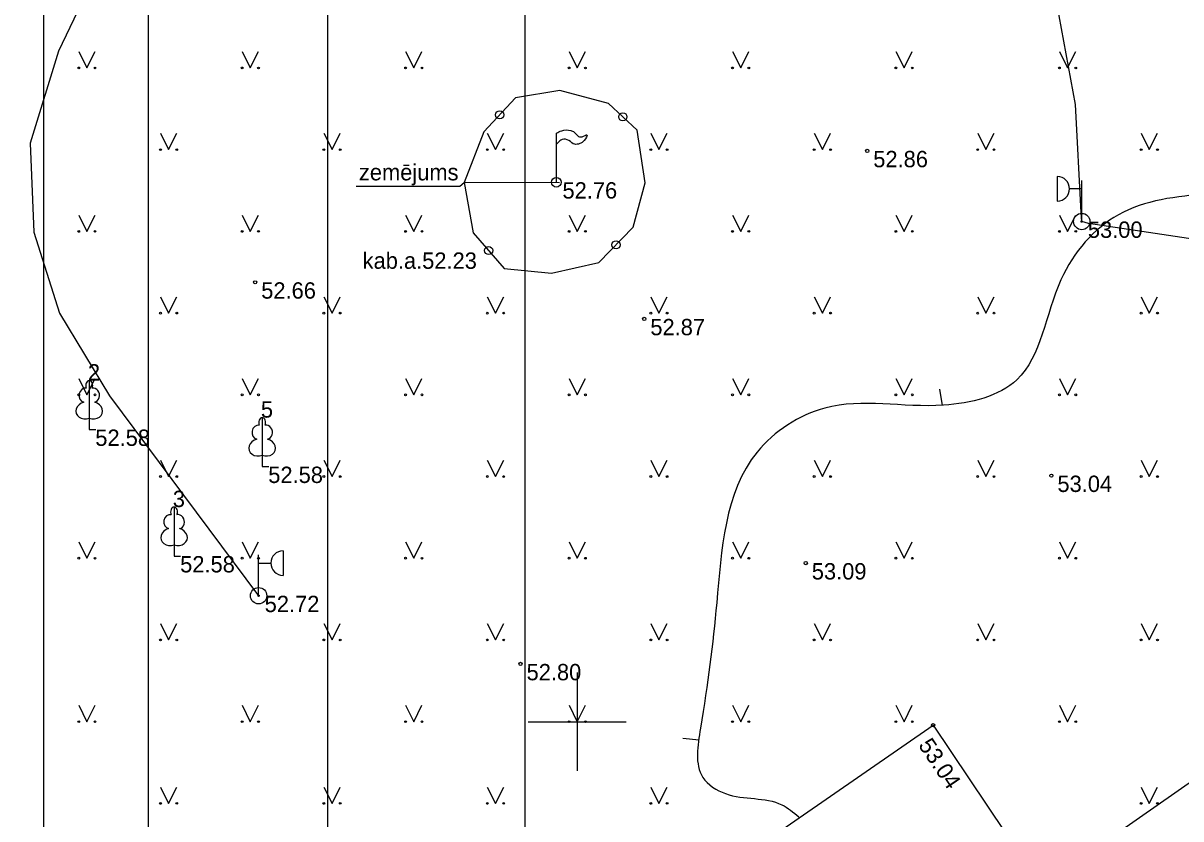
# Model space of a CAD drawing. Extents: x 619806 to 620082, y 405176 to 405386.
# Drawn here: x 619933.05 to 619968.46, y 405297.03 to 405321.37 of the extents above; entities that cross this region are included whole.
import ezdxf

# ---------------------------------------------------------------- set-up
doc = ezdxf.new("R2010")
doc.units = 0
for name, color, linetype in [('APGS_ELEM_####_####_#', 7, 'Continuous'), ('APGS_VADP_ZSPR_####_I', 7, 'Continuous'), ('BUVE_ELEM_####_####_#', 7, 'Continuous'), ('CELI_CMAL_####_####_#', 7, 'Continuous'), ('CKOM_ELEM_####_####_#', 7, 'Continuous'), ('CKOM_ZEMJ_####_####_#', 7, 'Continuous'), ('CKOM_ZEMJ_####_TKST_#', 7, 'Continuous'), ('GEOD_ELEM_####_####_#', 7, 'Continuous'), ('RAMI_PLAN_####_TKST_#', 7, 'Continuous'), ('RELJ_AATZ_####_TKST_#', 7, 'Continuous'), ('RELJ_ELEM_####_####_#', 7, 'Continuous'), ('RELJ_HORZ_PAMT_####_#', 7, 'Continuous'), ('TERT_DIAM_####_TKST_#', 7, 'Continuous'), ('TERT_ELEM_####_####_#', 7, 'Continuous')]:
    doc.layers.add(name, color=color, linetype=linetype)

msp = doc.modelspace()

# ---------------------------------------------------------------- linework, layer by layer
at = {"layer": 'APGS_ELEM_####_####_#'}
for p, q in [((619964.685, 405316.677), (619964.685, 405315.927)), ((619965.435, 405315.302), (619965.435, 405316.552)), ((619965.435, 405316.302), (619965.06, 405316.302)), ((619941.003, 405305.227), (619941.003, 405304.477)), ((619940.253, 405303.852), (619940.253, 405305.102)), ((619940.253, 405304.852), (619940.628, 405304.852))]:
    msp.add_line(p, q, dxfattribs=at)
for centre, radius in [((619965.435, 405315.302), 0.25), ((619965.435, 405315.302), 0.0225), ((619940.253, 405303.852), 0.25), ((619940.253, 405303.852), 0.0225)]:
    msp.add_circle(centre, radius, dxfattribs=at)
for centre, start, end in [((619964.685, 405316.302), 270, 90), ((619941.003, 405304.852), 90, 270)]:
    msp.add_arc(centre, 0.375, start, end, dxfattribs=at)
at = {"layer": 'APGS_VADP_ZSPR_####_I'}
for points in [[(619935.65, 405323.694), (619934.135, 405320.515), (619933.268, 405317.7), (619933.38, 405314.98), (619934.16, 405312.498), (619935.696, 405309.965), (619940.253, 405303.852)], [(619972.163, 405314.266), (619965.642, 405315.238), (619965.435, 405315.302), (619965.418, 405315.579), (619965.238, 405318.885), (619964.67, 405321.977)]]:
    msp.add_lwpolyline(points, dxfattribs=at)
at = {"layer": 'BUVE_ELEM_####_####_#'}
for p, q in [((619949.363, 405317.667), (619949.363, 405318.004)), ((619949.363, 405316.504), (619949.363, 405317.667))]:
    msp.add_line(p, q, dxfattribs=at)
msp.add_circle((619949.363, 405316.504), 0.148, dxfattribs=at)
msp.add_spline([(619949.363, 405318.004), (619949.525, 405318.078), (619949.801, 405318.087), (619949.907, 405318.034), (619950.044, 405317.907), (619950.149, 405317.895), (619950.299, 405317.952), (619950.213, 405317.78), (619950.076, 405317.685), (619949.924, 405317.664), (619949.748, 405317.78), (619949.536, 405317.806), (619949.468, 405317.765), (619949.363, 405317.667)], degree=3, dxfattribs=at)
at = {"layer": 'CELI_CMAL_####_####_#'}
msp.add_lwpolyline([(619951.468, 405293.381), (619960.885, 405299.892), (619964.19, 405294.965), (619971.285, 405299.927), (619977.055, 405303.943), (619973.673, 405308.787), (619991.854, 405321.355)], dxfattribs=at)
at = {"layer": 'CKOM_ELEM_####_####_#'}
for centre in [(619947.63, 405318.567), (619951.395, 405318.505), (619947.29, 405314.413), (619951.187, 405314.589)]:
    msp.add_circle(centre, 0.125, dxfattribs=at)
at = {"layer": 'CKOM_ZEMJ_####_####_#'}
msp.add_lwpolyline([(619949.455, 405316.486), (619946.54, 405316.495), (619946.816, 405314.959), (619947.764, 405313.868), (619949.217, 405313.72), (619950.66, 405314.051), (619951.714, 405315.127), (619952.08, 405316.486), (619951.831, 405318.095), (619950.958, 405318.914), (619949.472, 405319.305), (619948.114, 405319.086), (619947.145, 405318.049), (619946.54, 405316.495)], dxfattribs=at)
at = {"layer": 'CKOM_ZEMJ_####_TKST_#'}
for p, q in [((619943.242, 405316.387), (619946.408, 405316.387)), ((619946.408, 405316.387), (619946.54, 405316.495))]:
    msp.add_line(p, q, dxfattribs=at)
at = {"layer": 'GEOD_ELEM_####_####_#'}
for p, q in [((619950, 405301.5), (619950, 405300)), ((619948.5, 405300), (619950, 405300)), ((619950, 405300), (619950, 405298.5)), ((619950, 405300), (619951.5, 405300))]:
    msp.add_line(p, q, dxfattribs=at)
at = {"layer": 'RAMI_PLAN_####_TKST_#'}
msp.add_line((619942.357, 405361.716), (619942.357, 405215.404), dxfattribs=at)
for points in [[(619933.685, 405385.595), (620082.185, 405385.595), (620082.185, 405175.595), (619933.685, 405175.595)], [(619805.793, 405180.095), (619805.793, 405373.209), (619948.393, 405373.209), (619948.393, 405180.095)], [(619936.885, 405180.095), (619936.885, 405373.209), (620079.485, 405373.209), (620079.485, 405180.095)]]:
    msp.add_lwpolyline(points, close=True, dxfattribs=at)
at = {"layer": 'RELJ_ELEM_####_####_#'}
for centre in [(619958.87, 405317.462), (619940.148, 405313.442), (619952.051, 405312.322), (619964.504, 405307.527), (619956.99, 405304.85), (619948.265, 405301.766), (619960.885, 405299.892)]:
    msp.add_circle(centre, 0.05, dxfattribs=at)
at = {"layer": 'RELJ_HORZ_PAMT_####_#'}
for p, q in [((619961.087, 405310.169), (619961.165, 405309.675)), ((619953.233, 405299.495), (619953.731, 405299.445))]:
    msp.add_line(p, q, dxfattribs=at)
msp.add_spline([(619981.917, 405331.06), (619983.458, 405327.733), (619983.458, 405326.44), (619981.371, 405324.921), (619975.066, 405321.914), (619973.572, 405320.043), (619972.785, 405317.322), (619969.353, 405316.166), (619966.558, 405315.51), (619964.797, 405313.519), (619963.449, 405310.459), (619961.207, 405309.682), (619957.576, 405309.593), (619955.503, 405308.248), (619954.267, 405303.638), (619953.77, 405299.801), (619953.847, 405298.296), (619954.537, 405297.798), (619956.258, 405297.458), (619956.781, 405297.091)], degree=3, dxfattribs=at)
at = {"layer": 'TERT_ELEM_####_####_#'}
for p, q in [((619934.75, 405320.5), (619935, 405320)), ((619935, 405320), (619935.25, 405320.5)), ((619939.75, 405320.5), (619940, 405320)), ((619940, 405320), (619940.25, 405320.5)), ((619944.75, 405320.5), (619945, 405320)), ((619945, 405320), (619945.25, 405320.5)), ((619949.75, 405320.5), (619950, 405320)), ((619950, 405320), (619950.25, 405320.5)), ((619954.75, 405320.5), (619955, 405320)), ((619955, 405320), (619955.25, 405320.5)), ((619959.75, 405320.5), (619960, 405320)), ((619960, 405320), (619960.25, 405320.5)), ((619964.75, 405320.5), (619965, 405320)), ((619965, 405320), (619965.25, 405320.5)), ((619937.25, 405318), (619937.5, 405317.5)), ((619937.5, 405317.5), (619937.75, 405318)), ((619942.25, 405318), (619942.5, 405317.5)), ((619942.5, 405317.5), (619942.75, 405318)), ((619947.25, 405318), (619947.5, 405317.5)), ((619947.5, 405317.5), (619947.75, 405318)), ((619952.25, 405318), (619952.5, 405317.5)), ((619952.5, 405317.5), (619952.75, 405318)), ((619957.25, 405318), (619957.5, 405317.5)), ((619957.5, 405317.5), (619957.75, 405318)), ((619962.25, 405318), (619962.5, 405317.5)), ((619962.5, 405317.5), (619962.75, 405318)), ((619967.25, 405318), (619967.5, 405317.5)), ((619967.5, 405317.5), (619967.75, 405318)), ((619934.75, 405315.5), (619935, 405315)), ((619935, 405315), (619935.25, 405315.5)), ((619939.75, 405315.5), (619940, 405315)), ((619940, 405315), (619940.25, 405315.5)), ((619944.75, 405315.5), (619945, 405315)), ((619945, 405315), (619945.25, 405315.5)), ((619949.75, 405315.5), (619950, 405315)), ((619950, 405315), (619950.25, 405315.5)), ((619954.75, 405315.5), (619955, 405315)), ((619955, 405315), (619955.25, 405315.5)), ((619959.75, 405315.5), (619960, 405315)), ((619960, 405315), (619960.25, 405315.5)), ((619964.75, 405315.5), (619965, 405315)), ((619965, 405315), (619965.25, 405315.5)), ((619937.25, 405313), (619937.5, 405312.5)), ((619937.5, 405312.5), (619937.75, 405313)), ((619942.25, 405313), (619942.5, 405312.5)), ((619942.5, 405312.5), (619942.75, 405313)), ((619947.25, 405313), (619947.5, 405312.5)), ((619947.5, 405312.5), (619947.75, 405313)), ((619952.25, 405313), (619952.5, 405312.5)), ((619952.5, 405312.5), (619952.75, 405313)), ((619957.25, 405313), (619957.5, 405312.5)), ((619957.5, 405312.5), (619957.75, 405313)), ((619962.25, 405313), (619962.5, 405312.5)), ((619962.5, 405312.5), (619962.75, 405313)), ((619967.25, 405313), (619967.5, 405312.5)), ((619967.5, 405312.5), (619967.75, 405313)), ((619934.75, 405310.5), (619935, 405310)), ((619935, 405310), (619935.25, 405310.5)), ((619939.75, 405310.5), (619940, 405310)), ((619940, 405310), (619940.25, 405310.5)), ((619944.75, 405310.5), (619945, 405310)), ((619945, 405310), (619945.25, 405310.5)), ((619949.75, 405310.5), (619950, 405310)), ((619950, 405310), (619950.25, 405310.5)), ((619954.75, 405310.5), (619955, 405310)), ((619955, 405310), (619955.25, 405310.5)), ((619959.75, 405310.5), (619960, 405310)), ((619960, 405310), (619960.25, 405310.5)), ((619964.75, 405310.5), (619965, 405310)), ((619965, 405310), (619965.25, 405310.5)), ((619935.072, 405309.284), (619935.072, 405308.937)), ((619935.072, 405308.937), (619935.272, 405308.937)), ((619940.363, 405308.149), (619940.363, 405307.802)), ((619937.25, 405308), (619937.5, 405307.5)), ((619937.5, 405307.5), (619937.75, 405308)), ((619940.363, 405307.802), (619940.563, 405307.802)), ((619942.25, 405308), (619942.5, 405307.5)), ((619942.5, 405307.5), (619942.75, 405308)), ((619947.25, 405308), (619947.5, 405307.5)), ((619947.5, 405307.5), (619947.75, 405308)), ((619952.25, 405308), (619952.5, 405307.5)), ((619952.5, 405307.5), (619952.75, 405308)), ((619957.25, 405308), (619957.5, 405307.5)), ((619957.5, 405307.5), (619957.75, 405308)), ((619962.25, 405308), (619962.5, 405307.5)), ((619962.5, 405307.5), (619962.75, 405308)), ((619967.25, 405308), (619967.5, 405307.5)), ((619967.5, 405307.5), (619967.75, 405308)), ((619934.75, 405305.5), (619935, 405305)), ((619935, 405305), (619935.25, 405305.5)), ((619937.668, 405305.413), (619937.668, 405305.066)), ((619939.75, 405305.5), (619940, 405305)), ((619940, 405305), (619940.25, 405305.5)), ((619944.75, 405305.5), (619945, 405305)), ((619945, 405305), (619945.25, 405305.5)), ((619949.75, 405305.5), (619950, 405305)), ((619950, 405305), (619950.25, 405305.5)), ((619954.75, 405305.5), (619955, 405305)), ((619955, 405305), (619955.25, 405305.5)), ((619959.75, 405305.5), (619960, 405305)), ((619960, 405305), (619960.25, 405305.5)), ((619964.75, 405305.5), (619965, 405305)), ((619965, 405305), (619965.25, 405305.5)), ((619937.668, 405305.066), (619937.868, 405305.066)), ((619937.25, 405303), (619937.5, 405302.5)), ((619937.5, 405302.5), (619937.75, 405303)), ((619942.25, 405303), (619942.5, 405302.5)), ((619942.5, 405302.5), (619942.75, 405303)), ((619947.25, 405303), (619947.5, 405302.5)), ((619947.5, 405302.5), (619947.75, 405303)), ((619952.25, 405303), (619952.5, 405302.5)), ((619952.5, 405302.5), (619952.75, 405303)), ((619957.25, 405303), (619957.5, 405302.5)), ((619957.5, 405302.5), (619957.75, 405303)), ((619962.25, 405303), (619962.5, 405302.5)), ((619962.5, 405302.5), (619962.75, 405303)), ((619967.25, 405303), (619967.5, 405302.5)), ((619967.5, 405302.5), (619967.75, 405303)), ((619934.75, 405300.5), (619935, 405300)), ((619935, 405300), (619935.25, 405300.5)), ((619939.75, 405300.5), (619940, 405300)), ((619940, 405300), (619940.25, 405300.5)), ((619944.75, 405300.5), (619945, 405300)), ((619945, 405300), (619945.25, 405300.5)), ((619949.75, 405300.5), (619950, 405300)), ((619950, 405300), (619950.25, 405300.5)), ((619954.75, 405300.5), (619955, 405300)), ((619955, 405300), (619955.25, 405300.5)), ((619959.75, 405300.5), (619960, 405300)), ((619960, 405300), (619960.25, 405300.5)), ((619964.75, 405300.5), (619965, 405300)), ((619965, 405300), (619965.25, 405300.5)), ((619937.25, 405298), (619937.5, 405297.5)), ((619937.5, 405297.5), (619937.75, 405298)), ((619942.25, 405298), (619942.5, 405297.5)), ((619942.5, 405297.5), (619942.75, 405298)), ((619947.25, 405298), (619947.5, 405297.5)), ((619947.5, 405297.5), (619947.75, 405298)), ((619952.25, 405298), (619952.5, 405297.5)), ((619952.5, 405297.5), (619952.75, 405298)), ((619967.25, 405298), (619967.5, 405297.5)), ((619967.5, 405297.5), (619967.75, 405298))]:
    msp.add_line(p, q, dxfattribs=at)
for points in [[(619935.072, 405310.437), (619935.072, 405309.284)], [(619935.162, 405310.205), (619935.161, 405310.206)], [(619940.363, 405309.302), (619940.363, 405308.149)], [(619940.453, 405309.07), (619940.452, 405309.071)], [(619937.668, 405306.566), (619937.668, 405305.413)], [(619937.758, 405306.334), (619937.757, 405306.335)]]:
    msp.add_lwpolyline(points, dxfattribs=at)
for centre, radius in [((619934.75, 405320), 0.028), ((619935.25, 405320), 0.0263), ((619939.75, 405320), 0.028), ((619940.25, 405320), 0.0263), ((619944.75, 405320), 0.028), ((619945.25, 405320), 0.0263), ((619949.75, 405320), 0.028), ((619950.25, 405320), 0.0263), ((619954.75, 405320), 0.028), ((619955.25, 405320), 0.0263), ((619959.75, 405320), 0.028), ((619960.25, 405320), 0.0263), ((619964.75, 405320), 0.028), ((619965.25, 405320), 0.0263), ((619937.25, 405317.5), 0.028), ((619937.75, 405317.5), 0.0263), ((619942.25, 405317.5), 0.028), ((619942.75, 405317.5), 0.0263), ((619947.25, 405317.5), 0.028), ((619947.75, 405317.5), 0.0263), ((619952.25, 405317.5), 0.028), ((619952.75, 405317.5), 0.0263), ((619957.25, 405317.5), 0.028), ((619957.75, 405317.5), 0.0263), ((619962.25, 405317.5), 0.028), ((619962.75, 405317.5), 0.0263), ((619967.25, 405317.5), 0.028), ((619967.75, 405317.5), 0.0263), ((619934.75, 405315), 0.028), ((619935.25, 405315), 0.0263), ((619939.75, 405315), 0.028), ((619940.25, 405315), 0.0263), ((619944.75, 405315), 0.028), ((619945.25, 405315), 0.0263), ((619949.75, 405315), 0.028), ((619950.25, 405315), 0.0263), ((619954.75, 405315), 0.028), ((619955.25, 405315), 0.0263), ((619959.75, 405315), 0.028), ((619960.25, 405315), 0.0263), ((619964.75, 405315), 0.028), ((619965.25, 405315), 0.0263), ((619937.25, 405312.5), 0.028), ((619937.75, 405312.5), 0.0263), ((619942.25, 405312.5), 0.028), ((619942.75, 405312.5), 0.0263), ((619947.25, 405312.5), 0.028), ((619947.75, 405312.5), 0.0263), ((619952.25, 405312.5), 0.028), ((619952.75, 405312.5), 0.0263), ((619957.25, 405312.5), 0.028), ((619957.75, 405312.5), 0.0263), ((619962.25, 405312.5), 0.028), ((619962.75, 405312.5), 0.0263), ((619967.25, 405312.5), 0.028), ((619967.75, 405312.5), 0.0263), ((619934.75, 405310), 0.028), ((619935.25, 405310), 0.0263), ((619939.75, 405310), 0.028), ((619940.25, 405310), 0.0263), ((619944.75, 405310), 0.028), ((619945.25, 405310), 0.0263), ((619949.75, 405310), 0.028), ((619950.25, 405310), 0.0263), ((619954.75, 405310), 0.028), ((619955.25, 405310), 0.0263), ((619959.75, 405310), 0.028), ((619960.25, 405310), 0.0263), ((619964.75, 405310), 0.028), ((619965.25, 405310), 0.0263), ((619937.25, 405307.5), 0.028), ((619937.75, 405307.5), 0.0263), ((619942.25, 405307.5), 0.028), ((619942.75, 405307.5), 0.0263), ((619947.25, 405307.5), 0.028), ((619947.75, 405307.5), 0.0263), ((619952.25, 405307.5), 0.028), ((619952.75, 405307.5), 0.0263), ((619957.25, 405307.5), 0.028), ((619957.75, 405307.5), 0.0263), ((619962.25, 405307.5), 0.028), ((619962.75, 405307.5), 0.0263), ((619967.25, 405307.5), 0.028), ((619967.75, 405307.5), 0.0263), ((619934.75, 405305), 0.028), ((619935.25, 405305), 0.0263), ((619939.75, 405305), 0.028), ((619940.25, 405305), 0.0263), ((619944.75, 405305), 0.028), ((619945.25, 405305), 0.0263), ((619949.75, 405305), 0.028), ((619950.25, 405305), 0.0263), ((619954.75, 405305), 0.028), ((619955.25, 405305), 0.0263), ((619959.75, 405305), 0.028), ((619960.25, 405305), 0.0263), ((619964.75, 405305), 0.028), ((619965.25, 405305), 0.0263), ((619937.25, 405302.5), 0.028), ((619937.75, 405302.5), 0.0263), ((619942.25, 405302.5), 0.028), ((619942.75, 405302.5), 0.0263), ((619947.25, 405302.5), 0.028), ((619947.75, 405302.5), 0.0263), ((619952.25, 405302.5), 0.028), ((619952.75, 405302.5), 0.0263), ((619957.25, 405302.5), 0.028), ((619957.75, 405302.5), 0.0263), ((619962.25, 405302.5), 0.028), ((619962.75, 405302.5), 0.0263), ((619967.25, 405302.5), 0.028), ((619967.75, 405302.5), 0.0263), ((619934.75, 405300), 0.028), ((619935.25, 405300), 0.0263), ((619939.75, 405300), 0.028), ((619940.25, 405300), 0.0263), ((619944.75, 405300), 0.028), ((619945.25, 405300), 0.0263), ((619949.75, 405300), 0.028), ((619950.25, 405300), 0.0263), ((619954.75, 405300), 0.028), ((619955.25, 405300), 0.0263), ((619959.75, 405300), 0.028), ((619960.25, 405300), 0.0263), ((619964.75, 405300), 0.028), ((619965.25, 405300), 0.0263), ((619937.25, 405297.5), 0.028), ((619937.75, 405297.5), 0.0263), ((619942.25, 405297.5), 0.028), ((619942.75, 405297.5), 0.0263), ((619947.25, 405297.5), 0.028), ((619947.75, 405297.5), 0.0263), ((619952.25, 405297.5), 0.028), ((619952.75, 405297.5), 0.0263), ((619967.25, 405297.5), 0.028), ((619967.75, 405297.5), 0.0263)]:
    msp.add_circle(centre, radius, dxfattribs=at)
for centre, major_axis, ratio, start_param, end_param in [((619934.944, 405309.992), (-0.039, -0.212), 0.861323, 3.141593, 6.283185), ((619935.072, 405310.287), (0, -0.15), 0.707107, 3.14537, 5.287485), ((619935.072, 405310.287), (0, -0.15), 0.707107, 0.995701, 3.137816), ((619935.2, 405309.992), (0.039, -0.212), 0.861323, 0, 3.141593), ((619934.982, 405309.53), (0.307, 0.095), 0.814445, 1.570796, 4.752015), ((619935.162, 405309.53), (-0.307, 0.095), 0.814445, 1.531171, 4.712389), ((619940.363, 405309.152), (0, -0.15), 0.707107, 3.14537, 5.287485), ((619940.363, 405309.152), (0, -0.15), 0.707107, 0.995701, 3.137816), ((619940.235, 405308.857), (-0.039, -0.212), 0.861323, 3.141593, 6.283185), ((619940.491, 405308.857), (0.039, -0.212), 0.861323, 0, 3.141593), ((619940.273, 405308.395), (0.307, 0.095), 0.814445, 1.570796, 4.752015), ((619940.453, 405308.395), (-0.307, 0.095), 0.814445, 1.531171, 4.712389), ((619937.54, 405306.121), (-0.039, -0.212), 0.861323, 3.141593, 6.283185), ((619937.668, 405306.416), (0, -0.15), 0.707107, 3.14537, 5.287485), ((619937.668, 405306.416), (0, -0.15), 0.707107, 0.995701, 3.137816), ((619937.796, 405306.121), (0.039, -0.212), 0.861323, 0, 3.141593), ((619937.578, 405305.659), (0.307, 0.095), 0.814445, 1.570796, 4.752015), ((619937.758, 405305.659), (-0.307, 0.095), 0.814445, 1.531171, 4.712389)]:
    msp.add_ellipse(centre, major_axis=major_axis, ratio=ratio, start_param=start_param, end_param=end_param, dxfattribs=at)

# ---------------------------------------------------------------- texts
at = {"layer": 'CKOM_ZEMJ_####_TKST_#'}
for s, p in [('zemējums', (619943.322, 405316.56)), ('kab.a.52.23', (619943.436, 405313.855))]:
    msp.add_text(s, height=0.5, dxfattribs=at).set_placement(p)
at = {"layer": 'RELJ_AATZ_####_TKST_#'}
for s, p in [(' 52.86', (619958.87, 405316.962)), (' 52.76', (619949.363, 405316.004)), (' 53.00', (619965.435, 405314.802)), (' 52.66', (619940.148, 405312.942)), (' 52.87', (619952.051, 405311.822)), (' 52.58', (619935.072, 405308.437)), (' 52.58', (619940.363, 405307.302)), (' 53.04', (619964.504, 405307.027)), (' 52.58', (619937.668, 405304.566)), (' 53.09', (619956.99, 405304.35)), (' 52.72', (619940.253, 405303.352)), (' 52.80', (619948.265, 405301.266))]:
    msp.add_text(s, height=0.5, dxfattribs=at).set_placement(p)
msp.add_text(' 53.04', height=0.5, rotation=303.8535, dxfattribs=at).set_placement((619960.315, 405299.433))
at = {"layer": 'TERT_DIAM_####_TKST_#'}
for s, p in [(' 2', (619934.847, 405310.437)), (' 5', (619940.138, 405309.302)), (' 3', (619937.443, 405306.566))]:
    msp.add_text(s, height=0.5, dxfattribs=at).set_placement(p)

doc.saveas('drawing.dxf')
